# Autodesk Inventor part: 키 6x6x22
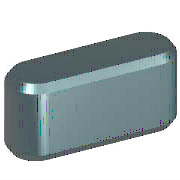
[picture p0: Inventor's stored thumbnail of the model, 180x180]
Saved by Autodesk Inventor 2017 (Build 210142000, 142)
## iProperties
IsCustomPart: 1
Created: 2012-02
Part Number: 키 6x6x22
Material: 강철, 연강
Description: 키 및 해당 키홈
Document SubType Name: Modeling
Standard: KS B 1311
Designer: mduedu
Standards Organization: KS
Language: ko-KR
Size Designation: 6 x 6 x 22
Categories: <MemberInstance><Categories><Category DisplayName="샤프트 부품" InternalName="7f7aeb1f-a693-4053-b835-cee3144e0d98" Mnemonic="SHFT"><Category DisplayName="키" Interna
Density: 7.86 g/cm^3
Mass: 5.79788 g
Surface Area: 5.294 cm^2
Volume: 0.737644 cm^3
Appearance: 노란색
Author: mduedu
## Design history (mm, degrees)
workplane "Work Plane1"
workplane "Work Plane2"
sketch "스케치1"
  geometry: L1 (3, 3)-(19, 3); L2 (19, -3)-(3, -3); L3 (0, 9.4)-(0, -7.4) reference; L4 (-5, 0)-(30, 0) reference; L5 (22, 0)-(22, 7); A1 r 3 centre (3, 0) between (3, 3) and (3, -3); A2 r 3 centre (19, 0) between (19, -3) and (19, 3)
  constraints: 6 end point, 5 point on circle, 4 tangent, 3 point on line, 2 centre point, 1 horizontal, 1 parallel, 1 perpendicular
  dimensions: "d0" = 3 radius of A1 (= 0.5 x PB); "d13" = 3 radius of A2 (= 0.5 x PB); "d14" = 22 distance between parallel lines of L5 L3 (= NLG)
extrude "본체1" new body sketch "스케치1" taper "d3" = 0 deg; stored distance "d4" = 10
workplane "Work Plane3"
body "Solid1"
chamfer "모따기1" distance "d8" = 0.4 (= PHH); stored, may be unused: second distance "d9" = 0.4 (= PHH), angle "d15" = 45 deg
other parameters: "d1" = -3.5 (= -PNT), "d2" = 2.5 (= PH - PNT), "NLG" = 22 [user parameter; used in 3 equation terms], "PB" = 6 [user parameter; used in 2 equation terms], "PNT" = 3.5 [user parameter; used in 2 equation terms], "PH" = 6 [user parameter; used in 1 equation term], "PHH" = 0.4 [user parameter; used in 2 equation terms], "d10" = 0, "d16" = 0, "d17" = 0, "d18" = 0, "WDMIN" = 17 [user parameter], "PLB2" = 22 (= NLG) [user parameter], "WDMAX" = 22 [user parameter], "PLB1" = 22 (= NLG) [user parameter], "RR" = 0.16 [user parameter], "PUEB" = 2.8 [user parameter]
